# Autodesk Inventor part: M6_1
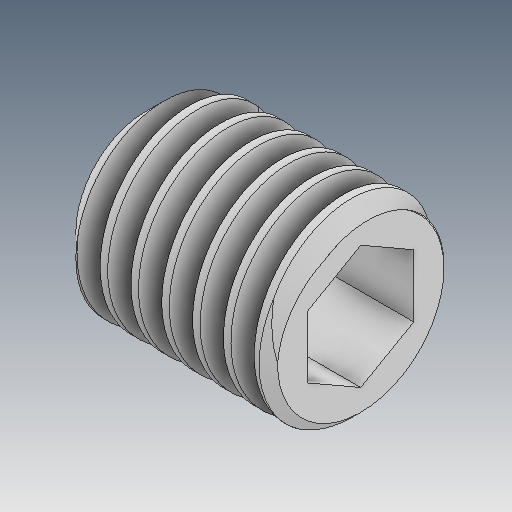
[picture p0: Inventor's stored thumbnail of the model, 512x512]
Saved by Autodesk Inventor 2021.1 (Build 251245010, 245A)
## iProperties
Created: 2019-04
Part Number: M6_1
Material: Ogólny
Document SubType Name: Modeling
Designer: user
Density: 1 g/cm^3
Appearance: Domyślna
Author: user
Revision Number: ÈÎºÎ
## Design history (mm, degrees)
feature "ÊäÈë1"
node "Bryła1"
